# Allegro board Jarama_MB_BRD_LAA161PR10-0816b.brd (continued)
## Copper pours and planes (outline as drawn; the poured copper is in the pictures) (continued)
DCIN_GND on TOP (solid shape): 33.84,68.97 33.84,67.17 33.58,66.91 30.03,66.91 29.52,67.42 29.52,68.69 29.9,69.07 33.74,69.07
DCIN_GND on BOTTOM (solid shape): 33.85,68.94 33.85,65.51 33.72,65.39 32.07,65.39 30.68,66.78 30.68,68.94 30.8,69.07 33.72,69.07
DH_+1.2V on TOP (solid shape): 87.31,31.53 87.31,30.56 87.23,30.49 86.39,30.49 86.29,30.59 86.29,31.48 86.42,31.61 87.23,31.61
DH_+1.2V on BOTTOM (solid shape): 95.69,33.83 94.85,33.83 94.56,33.54 94.56,33.43 94.46,33.33 93.56,33.33 93.42,33.47 93.42,33.83 93.63,34.04 95.69,34.04
DH_+1.2V on IN1 (solid shape): 87.57,32.24 87.57,30.59 87.19,30.21 86.68,30.21 86.43,30.46 86.43,32.24 86.56,32.37 87.45,32.37
DH_+1.2V on IN1 (solid shape): 94.81,34.02 94.81,33.51 94.56,33.26 92.65,33.26 92.4,33.51 92.4,34.15 92.53,34.27 94.56,34.27
DL_+1.2V on TOP (solid shape): 88.38,34.98 88.38,33.85 88.29,33.76 87.56,33.76 87.31,34.02 87.31,34.6 87.21,34.7 87.21,35.08 87.29,35.16 88.19,35.16
DL_+1.2V on BOTTOM (solid shape): 96.13,33.1 96.13,32.39 95.37,31.63 94.89,31.63 94.68,31.83 94.68,31.99 95.83,33.13 96.11,33.13
DL_+1.2V on IN3 (solid shape): 89.35,34.65 89.35,34.02 89.22,33.89 87.83,33.89 87.32,34.4 87.32,35.03 87.45,35.16 88.84,35.16
DL_+1.2V on IN3 (solid shape): 95.83,32.49 95.83,31.86 95.07,31.1 94.05,31.1 94.05,32.11 94.43,32.11 95.07,32.75 95.57,32.75
HP2_D_R_C on TOP: 13.14,15.98 15.27,15.98 15.32,15.93 15.32,14.87 15.53,14.66 15.8,14.66 16.03,14.44 16.03,13.93 15.75,13.65 14.79,13.65 14.08,14.36 14.08,14.74 13.99,14.83 12.33,14.83 12.33,15.17
KB_LED_PWM# on BOTTOM: 155.01,8.75 156.66,8.75 156.91,9 156.91,10.27 157.17,10.52 157.17,11.16 157.17,11.16 157.17,11.44 156.88,11.72 156.23,11.72 156.03,11.92 155.14,11.92 154.88,11.67 154.88,8.87
L_MIC1 on TOP (solid shape): 21.38,24.2 22.14,24.2 22.23,24.11 22.66,24.11 22.75,24.2 23.72,24.2 23.74,24.19 23.74,24.01 23.72,24 22.88,24 22.79,23.91 21.24,23.91 21.12,23.79 20.24,23.79 20.06,23.97 20.06,24.54 20.35,24.82 20.76,24.82
L_MIC1 on IN1 (solid shape): 16.45,6.28 16.45,5.29 16.32,5.17 14.82,5.17 14.68,5.3 14.68,6.23 14.84,6.4 16.33,6.4
L_MIC1 on BOTTOM: 16.09,5.15 15.83,5.41 15.83,6.32 16.87,7.36 16.87,8.53 15.7,9.71 15.7,10.16 15.96,10.42 17.12,10.42 17.28,10.58 17.28,12.8 17.3,12.81 18.55,12.81 18.76,13.02 19.59,13.02 19.74,12.87 19.74,10.07 18.71,9.04 18.71,6.19 17.66,5.15
L_MIC1 on IN1: 19.17,13.88 18.58,13.28 18.58,12.58 18.98,12.17 23.42,12.17 23.7,12.46 23.7,24.71 23.42,24.99 20.43,24.99 19.99,24.55 19.99,20.32 19.17,19.51
L_MIC1 on IN2: 3.22,1.49 2.54,2.17 2.54,4.18 2.8,4.44 3.96,4.44 4.22,4.18 4.22,3.54 4.52,3.24 10.47,3.24 12.05,4.82 12.25,5.22 12.1,5.63 14.17,7.7 15.49,7.7 17.24,9.45 17.24,13.3 20.96,17.02 20.96,20.19 22.66,21.89 22.66,23.85 22.58,23.93 20.86,23.93 20.61,23.68 20.05,23.68 19.84,23.89 19.84,25.59 20.48,26.23 23.44,26.23 23.73,25.93 23.73,16.68 20.09,13.04 20.09,8.31 16.97,5.2 14.04,5.2 10.33,1.49
LG_3V on TOP (solid shape): 192.87,37.55 192.87,37.22 191.45,35.8 191.32,35.8 191.26,35.86 191.26,36.72 191.32,36.79 191.52,36.79 191.67,36.94 191.67,37.5 191.83,37.65 192.77,37.65
LG_3V on TOP (solid shape): 193.5,44.64 193.5,44.43 193.15,44.08 193.15,43.32 193,43.16 192.54,43.16 192.39,43.32 192.39,44.66 192.51,44.79 193.35,44.79
LG_3V on IN2 (solid shape): 194.45,45.64 194.45,44.83 194.37,44.76 193.71,44.76 193.59,44.64 193.59,44.46 193.47,44.33 193.34,44.33 192.75,43.75 192.53,43.75 192.4,43.87 192.4,44.23 192.32,44.31 192.32,44.72 193.4,45.8 194.29,45.8
LG_3V on IN2 (solid shape): 192.83,38.16 192.6,37.93 192.6,37.24 192.45,37.09 191.48,37.09 191.45,37.13 191.53,37.43 191.36,37.69 191.36,38.59 191.84,39.07 192.83,39.07
LG_5V on TOP (solid shape): 189.46,40.72 189.46,36.99 189.67,36.79 189.79,36.79 189.86,36.72 189.86,35.82 189.8,35.76 189.68,35.76 188.74,36.7 188.74,38.76 187.51,39.99 187.51,40.8 187.69,40.98 189.21,40.98
LINE2-VREFO on TOP (solid shape): 22.89,25.03 23.83,25.03 23.91,24.95 23.91,24.85 23.83,24.77 22.84,24.77 22.76,24.85 22.36,24.85 21.88,24.37 21.47,24.37 21.29,24.54 21.29,24.72 21.49,24.93 22.13,24.93 22.26,25.05 22.87,25.05
LX_3V on TOP (solid shape): 196.55,44.26 196.55,43.77 195.94,43.16 195.51,43.16 195.38,43.29 195.38,44.18 195.51,44.31 196.5,44.31
LX_3V on TOP (solid shape): 194.77,35.23 194.77,34.23 194.71,34.17 193.3,34.17 192.79,34.68 191.75,34.68 191.75,34.83 191.8,34.88 193.12,34.88 193.58,35.34 194.66,35.34
LX_3V on IN1 (solid shape): 195.2,36.67 195.2,35.55 193.84,34.2 193.58,34.2 193.19,34.6 193.19,35.3 194.18,36.29 194.18,36.6 194.38,36.8 195.07,36.8
LX_3V on IN1 (solid shape): 196.68,44.37 196.68,43.81 196.18,43.31 196.18,41.74 196.15,41.71 195.19,41.71 195.16,41.74 195.16,44.22 195.49,44.54 196.51,44.54
LX_5V on TOP (solid shape): 185.22,40.88 185.22,40.06 185.1,39.94 184.33,39.94 184.21,40.06 184.21,40.64 184.58,41 185.1,41
LX_5V on TOP (solid shape): 187.89,34.88 189.52,34.88 189.58,34.82 189.58,34.74 189.52,34.68 188.35,34.68 187.64,33.97 186.61,33.97 186.48,34.09 186.48,35.03 186.51,35.06 187.71,35.06
LX_5V on IN2 (solid shape): 185.39,40.32 185.39,38.51 187.9,36 187.9,34.23 187.52,33.84 186.73,33.84 186.4,34.17 186.4,35.64 184.04,38.01 184.04,40.57 184.09,40.62 185.08,40.62
LX_DGPU on BOTTOM (solid shape): 100.78,51.8 100.78,46.94 100.77,46.94 100.34,46.68 100.55,46.22 100.38,46.08 100.31,45.87 98.24,43.8 94.61,43.8 94.61,42.99 97.12,42.99 97.12,41.28 96.59,40.75 93.92,40.75 93.54,41.13 93.54,44.43 94.94,45.83 94.94,47.23 97,49.29 97.79,49.29 97.99,49.49 97.99,52.03 98.03,52.07 100.51,52.07
MIC2-VREFO-L on TOP (solid shape): 29.83,22.15 29.83,21.32 29.72,21.22 28.89,21.22 28.78,21.32 28.78,22.16 28.84,22.21 29.77,22.21
P1 on TOP (solid shape): 77.65,14.97 77.65,11.67 77.4,11.41 74.1,11.41 73.79,11.72 73.79,13.5 73.87,13.57 75.37,13.57 75.49,13.7 75.49,14.33 73.72,14.33 73.72,15.1 77.53,15.1
REGN on TOP (solid shape): 97.47,8.36 97.47,7.81 97.72,7.55 97.72,6.84 97.59,6.71 96.83,6.71 96.45,7.09 95.56,7.09 95.43,7.22 95.43,7.6 96.45,8.62 97.21,8.62
REGN on BOTTOM (solid shape): 97.86,8.39 97.86,7.48 97.78,7.4 97.68,7.4 97.53,7.55 97.15,7.55 96.87,7.83 96.87,8.52 96.95,8.59 97.66,8.59
SKIP#1 on BOTTOM (solid shape): 100.07,55.29 100.07,53.75 100.06,53.74 99.11,53.74 98.91,53.54 98.91,53.14 98.82,53.04 98.06,53.04 97.99,53.12 97.99,54.14 99.21,55.36 100,55.36
SLEEVE on IN1 (solid shape): 16.73,11.16 16.73,10.97 16.21,10.45 15.98,10.45 14.65,11.78 14.65,12.06 15.11,12.52 15.37,12.52
SLEEVE on TOP: 15.68,15.9 15.68,18.65 15.8,18.78 16.44,18.78 16.57,18.65 16.57,16.87 16.69,16.75 16.74,16.75 16.9,16.59 16.9,16.36 17.05,16.21 17.05,15.93 16.89,15.77 15.81,15.77
SLEEVE on TOP: 21.61,23.8 23.73,23.8 23.74,23.79 23.74,23.61 23.73,23.6 22.74,23.6 22.45,23.31 21.64,23.31 21.52,23.43 21.52,23.71
SLEEVE on TOP: 14.88,12.84 15.64,12.84 16.63,11.85 16.63,10.74 16.47,10.57 16.2,10.57 15.09,11.67 14.8,11.67 14.47,12 14.47,12.43
SLEEVE on BOTTOM: 16.49,17.58 16.49,17.18 16.14,16.83 16.14,16.02 16.3,15.86 16.95,15.86 17.03,15.93 17.03,16.6 17.39,16.97 17.39,17.48 17.21,17.67 16.58,17.67
SLEEVE on IN2: 19.81,17.61 19.81,19.85 22.57,22.61 22.57,23.66 22.45,23.78 20.87,23.78 20.22,23.13 19.05,23.13 17.99,22.07 17.99,21.22 15.82,19.05 15.82,17.71 13.92,15.8 8.79,15.8 7.66,14.68 2.93,14.68 2.38,14.14 2.38,12.45 2.67,12.16 4.01,12.16 4.27,12.42 4.27,13.12 4.75,13.59 15.79,13.59
SNUB_1.5VSP on BOTTOM (solid shape): 90.49,52.05 90.49,50.4 90.37,50.27 89.48,50.27 89.48,50.91 88.97,51.42 88.97,52.18 90.37,52.18
SNUB_1.8VSP on BOTTOM (solid shape): 224.83,36.36 224.83,35.56 224.77,35.49 221.89,35.49 221.79,35.59 221.79,36.47 221.93,36.61 224.58,36.61
SNUB_3V on BOTTOM (solid shape): 195.6,46.9 195.6,45.91 195.55,45.86 194.58,45.86 194.25,45.53 194.25,45.02 193.26,45.02 193.16,45.12 193.16,46.8 193.34,46.97 195.52,46.97
SNUB_5V on BOTTOM (solid shape): 187.13,46.91 187.13,45.29 187.09,45.25 186.12,45.25 186,45.37 186,45.7 185.74,45.96 184.85,45.96 184.73,46.08 184.73,46.85 184.85,46.97 187.07,46.97
SNUB_+1.2V on BOTTOM (solid shape): 90.37,38.97 90.37,38.21 90.87,37.7 90.87,36.81 89.35,36.81 89.22,36.94 89.22,39.1 89.35,39.23 90.11,39.23
SNUB_+1.05V on BOTTOM (solid shape): 198.27,63.63 198.27,61.83 198.21,61.77 197.71,61.77 197.7,61.78 197.7,62.45 197.56,62.59 196.59,62.59 196.55,62.64 196.55,63.69 196.6,63.74 198.16,63.74
SNUB_CHG on BOTTOM (solid shape): 88.82,14.23 88.82,13.93 89.05,13.7 89.93,13.7 90.04,13.6 90.04,12.58 89.88,12.43 87.83,12.43 87.57,12.68 87.57,14.38 87.7,14.51 88.54,14.51
SPK_L+_C on TOP (solid shape): 20.79,15.41 21.03,15.35 21.27,15.42 23.5,15.42 24.27,14.65 24.27,13.8 24.66,13.41 24.66,12.77 24.63,12.74 23.61,12.74 23.5,12.84 23.5,13.79 22.71,14.58 21.18,14.58 21.09,14.49 21.06,14.49 21.06,14.46 20.94,14.34 20.68,14.34 20.58,14.44 20.58,15.34 20.66,15.42 20.78,15.42
SPK_L+_C on BOTTOM: 21.53,10.55 20.39,11.69 20.39,16.73 20.4,16.74 20.4,17.22 20.5,17.33 21.38,17.33 21.61,17.1 21.61,15.52 21.32,15.22 21.32,13.65 22.55,12.42 22.55,10.73 22.37,10.55
SPK_L-_C on TOP: 21.24,12.71 21.95,12.71 22.15,12.5 23.08,12.5 23.21,12.63 23.21,13.69 22.5,14.39 22.13,14.39 22.07,14.33 22.07,13.68 21.83,13.45 21.25,13.45 21.21,13.4 21.21,12.74
SPK_L-_C on BOTTOM: 23.13,10.52 23.56,10.52 23.82,10.78 23.82,17 23.44,17.38 22.57,17.38 22.45,17.25 22.45,15.05 22.72,14.78 22.72,12.89 22.99,12.61 22.99,10.66
SPK_OUT_L+ on TOP (solid shape): 24.92,12 24.92,11.86 25.94,10.85 25.94,9.02 25.87,8.95 25.73,8.95 25.67,9.01 25.67,9.85 25.67,9.85 25.67,9.92 24.16,11.43 23.7,11.43 23.57,11.56 23.57,12.19 23.62,12.24 24.68,12.24
SPK_OUT_L- on TOP (solid shape): 22.59,11.98 22.59,11.69 24.86,9.42 24.86,8.44 24.78,8.36 23.88,8.36 23.68,8.57 23.68,9.29 22.85,10.12 22.38,10.12 21.24,11.26 21.24,12.15 21.3,12.21 22.36,12.21
SPK_OUT_R+ on TOP (solid shape): 26.94,11.9 26.94,11.89 27.09,11.74 27.09,10.19 26.94,10.03 26.94,9.02 26.86,8.94 26.74,8.94 26.67,9.01 26.67,10.08 26.67,10.08 26.67,10.45 25.6,11.52 25.6,12.11 25.68,12.19 26.64,12.19
SPK_OUT_R- on TOP (solid shape): 28.82,11.95 28.82,8.46 28.72,8.37 27.81,8.37 27.76,8.43 27.76,10.9 27.42,11.24 27.42,12.15 27.5,12.22 28.55,12.22
SPK_R+_C on TOP (solid shape): 26.27,16.6 26.27,13.84 26.7,13.4 26.7,12.71 26.68,12.68 25.48,12.68 25.37,12.79 25.37,13.62 25.3,13.69 25.3,16.7 25.43,16.83 26.04,16.83
SPK_R+_C on BOTTOM: 24.81,10.55 24.45,10.55 24.25,10.75 24.25,16.75 24.8,17.29 25.66,17.29 26.13,16.82 26.13,15.79 25.33,14.99 25.33,12.72 25.05,12.44 25.05,10.79
SPK_R-_C on TOP (solid shape): 28.52,15.37 28.52,12.7 28.49,12.66 27.49,12.66 27.43,12.72 27.43,14.47 27.3,14.61 27.3,15.41 27.49,15.6 28.29,15.6
SPK_R-_C on BOTTOM: 26.24,10.52 25.71,10.52 25.51,10.73 25.51,12.38 26.61,13.48 26.61,15.41 26.4,15.63 26.4,17.12 26.63,17.34 27.36,17.34 27.5,17.2 27.5,15.83 27.82,15.52 27.82,13.11 26.49,11.78 26.49,10.77
SW_+1.2V on TOP (solid shape): 93.35,33.1 94.57,33.1 94.67,33 94.67,32.24 94.47,32.04 92.57,32.04 92.34,32.27 91.87,32.27 91.59,31.99 90.86,31.99 90.61,31.73 90.61,29.07 90.2,28.66 83.95,28.66 83.5,29.12 83.5,30.97 84,31.48 85.91,31.48 86.04,31.35 86.04,30.51 86.21,30.34 87.56,30.34 87.69,30.46 87.69,33.43 87.76,33.51 92.94,33.51
SW_+1.2V on BOTTOM (solid shape): 95.73,33.51 95.73,33.28 93.99,31.54 92.51,31.54 92.51,32.44 92.53,32.45 93,32.45 93.73,33.18 94.63,33.18 94.84,33.38 94.84,33.54 94.89,33.59 95.65,33.59
SW_+1.2V on BOTTOM (solid shape): 90.87,33.06 89.85,32.04 89.85,31.47 90,31.33 90,29.05 89.63,28.68 83.91,28.68 83.48,29.12 83.48,31.76 86.66,31.76 86.66,30.44 86.76,30.34 87.34,30.34 87.46,30.45 87.46,31.77 87.36,31.87 86.77,31.87 86.66,31.76 83.48,31.76 83.48,33.79 84.04,34.35 88.57,34.35 89.26,35.03 90.87,35.03
SW_+1.05VS on TOP (solid shape): 196.14,64.8 196.14,62.47 196.02,62.34 194.6,62.34 194.44,62.19 192.4,62.19 192.12,62.46 192.12,63.23 192.12,63.31 192.93,64.12 192.93,64.59 193.23,64.89 196.05,64.89
SW_+1.05VS on BOTTOM (solid shape): 199.46,66 199.46,64.63 199.21,64.37 196.92,64.37 196.31,63.76 196.31,59.63 196.1,59.42 194.32,59.42 194.12,59.62 194.12,60.31 193.62,60.82 193.62,61.45 193.24,61.83 192.35,61.83 192.12,62.06 192.12,63.01 192.6,63.49 192.6,64.96 193.97,66.33 199.13,66.33
UG_3V on TOP (solid shape): 193.66,36.89 193.66,36.25 193.55,36.15 193.15,36.15 192.46,35.47 191.6,35.47 191.55,35.52 191.55,35.64 192.97,37.07 193.48,37.07
UG_3V on TOP (solid shape): 196.93,43.32 196.93,42.43 196.75,42.25 196.35,42.25 196.09,42.5 195.64,42.5 195.48,42.65 195.48,42.83 195.59,42.93 196.07,42.93 196.55,43.42 196.83,43.42
UG_3V on BOTTOM (solid shape): 196.79,43.29 196.79,42.25 196.36,41.82 196.36,38.9 193.57,36.1 192.53,36.1 192.42,36.2 192.42,36.82 192.59,36.99 192.87,37.1 192.98,37.38 195.34,39.74 195.34,43.06 195.73,43.44 196.65,43.44
UG_5V on TOP (solid shape): 185.2,41.54 185.2,41.31 185.12,41.23 184.46,41.23 183.98,40.75 183.98,39.99 186.11,37.85 187.36,37.85 189.58,35.63 189.58,35.54 189.52,35.48 188.51,35.48 187.36,36.64 185.76,36.64 182.89,39.51 182.89,41.18 183.34,41.64 185.1,41.64
VLDOIN_+1.2V on BOTTOM (solid shape): 94.6,35.84 94.6,35.03 94.8,34.84 95.74,34.84 95.78,34.8 95.78,34.69 95.73,34.63 93.68,34.63 93.52,34.79 93.52,36.07 93.54,36.09 94.35,36.09
VRP on TOP: 24.64,21.88 24.69,21.83 24.69,20.56 24.57,20.43 24.57,20.05 24.19,19.67 22.92,19.67 22.79,19.79 22.79,20.18 23.04,20.43 24.06,20.43 24.44,20.81 24.44,21.83 24.49,21.88
VRP on BOTTOM: 24.96,18.14 24.58,17.76 23.18,17.76 22.8,18.14 22.8,20.21 22.92,20.33 24.72,20.33 24.96,20.09
N13374678 on TOP (solid shape): 196.12,58.83 196.56,58.39 196.56,58.31 196.91,57.97 196.91,57.51 197.16,57.26 197.67,57.26 197.8,57.13 197.8,56.62 197.67,56.5 197.16,56.5 197.03,56.62 197.03,56.88 196.91,57.01 196.14,57.01 195.94,57.21 195.94,59.72 196.12,59.72
N13374846 on TOP (solid shape): 197.54,66.15 197.54,65.39 197.41,65.26 196.54,65.26 196.31,65.49 195.2,65.49 195.12,65.58 195.12,66.21 195.18,66.28 197.41,66.28
N22841841 on TOP: 53.57,12.91 55.45,12.91 55.56,12.81 55.56,11.92 55.48,11.84 53.49,11.84 53.36,11.97 53.36,12.7
N39955939 on BOTTOM: 35.38,14.33 36.26,14.33 36.89,13.71 36.89,12.78 36.52,12.42 36.52,12.12 36.46,12.06 35.6,12.06 35.5,12.16 35.5,13.06 35.25,13.32 35.25,14.21
N39956029 on BOTTOM: 33.72,14.33 33.85,14.21 33.85,13.46 33.76,13.36 32.75,13.36 32.64,13.47 31.77,13.47 31.69,13.55 31.69,14.21 31.82,14.33
N42153733 on TOP (solid shape): 244.14,54.35 244.14,54.32 244.15,54.28 244.15,52.85 243.99,52.69 243.97,52.69 243.8,52.51 243.15,52.51 243.03,52.63 243.03,54.16 243.25,54.38 244.11,54.38
N43167321 on TOP (solid shape): 194.87,51.47 194.87,50.62 194.84,50.58 193.5,50.58 193.32,50.76 191.9,50.76 191.83,50.83 191.83,51.47 191.95,51.6 194.75,51.6
N43454026 on TOP (solid shape): 168.33,67.55 168.33,67.4 168.7,67.04 169.6,67.04 169.73,66.91 169.73,66.4 169.6,66.28 168.71,66.28 168.01,66.98 167.38,66.98 167.38,67.61 168.27,67.61
N44367556 on TOP (solid shape): 192.67,49.34 193.12,49.34 193.22,49.23 193.22,48.52 193.12,48.42 191.98,48.42 191.83,48.57 191.83,49.31 191.95,49.44 192.56,49.44
N44367556 on BOTTOM (solid shape): 193.24,49.44 193.24,48.9 193.28,48.85 193.28,48.63 193.14,48.49 192.11,48.49 191.96,48.64 191.96,49.51 192.01,49.56 193.11,49.56
N44369635 on TOP (solid shape): 190.61,49.34 190.61,48.45 190.3,48.14 188.19,48.14 188.02,48.32 188.02,49.06 188.14,49.18 189.57,49.18 189.76,49.38 190.57,49.38
N44369635 on BOTTOM (solid shape): 190.82,49.94 190.82,48.75 190.7,48.62 188.66,48.62 188.54,48.75 188.54,49.39 188.79,49.64 189.81,49.64 189.93,49.77 189.93,49.89 190.11,50.07 190.7,50.07
N44372336 on TOP: 243.08,51.2 243.9,51.2 244.51,51.81 245.15,51.81 245.23,51.73 245.23,50.83 245.02,50.63 244.02,50.63 243.86,50.47 243.13,50.47 243.03,50.57 243.03,51.15
N44536141 on TOP (solid shape): 169.73,69.58 169.73,68.56 169.6,68.44 167.44,68.44 167.32,68.56 167.32,69.45 167.57,69.71 169.6,69.71
N45346908 on TOP: 51.11,10.14 51.11,8.63 50.13,7.65 48.14,7.65 48.05,7.74 48.05,8.35 48.15,8.45 49.42,8.45 49.59,8.62 49.59,9.63 49.84,9.89 49.84,10.52 49.97,10.65 50.48,10.65 50.6,10.52 50.6,10.4 50.73,10.27 50.98,10.27
N45347302 on TOP: 238.18,47.23 236.66,47.23 236.53,47.1 236.53,46.21 236.91,45.83 238.56,45.83 238.69,45.96 238.69,46.72
N45348400 on TOP: 237.29,50.66 236.53,50.66 236.4,50.53 236.4,49.39 236.53,49.26 236.53,48.62 236.66,48.5 237.17,48.5 237.42,48.75 237.42,50.53
N47396970 on BOTTOM (solid shape): 229.05,38.84 229.05,37.57 228.82,37.35 225.37,37.35 225.09,37.63 225.09,39.68 225.29,39.89 228.01,39.89
N47396970 on TOP: 227.13,36.79 227.13,37.7 227.39,37.96 228.26,37.96 228.34,38.03 228.34,38.87 228.34,38.88 228.25,38.97 226.79,38.97 226.52,38.71 226.36,38.71 226.1,38.97 225.15,38.97 225.08,39.05 225.08,40.17 225.25,40.34 228.72,40.34 229.05,40 229.05,39.67 229.83,38.89 229.83,37.32 229.3,36.79
N47421956 on TOP (solid shape): 104.34,61.12 104.96,61.12 105.09,60.99 105.09,60.36 105.04,60.31 104.48,60.31 104.43,60.36 104.43,60.49 104.22,60.69 103.82,60.69 103.56,60.43 103.56,60.31 103.43,60.18 102.67,60.18 102.62,60.23 102.62,60.33 102.67,60.38 102.67,61.1 103.03,61.45 104.01,61.45
N47421965 on TOP (solid shape): 99.47,59.19 99.47,59.06 99.42,59.01 98.18,59.01 98.02,58.86 98.02,58.81 97.54,58.33 97.54,57.67 97.14,57.26 95.18,57.26 95.05,57.13 95.05,56.33 94.89,56.17 94.19,56.17 94.16,56.19 94.16,57.34 94.3,57.47 94.54,57.47 94.63,57.56 96.37,57.56 96.48,57.67 96.48,58.53 96.83,58.89 97.62,58.89 97.95,59.22 99.45,59.22
N47422085 on TOP (solid shape): 100.16,57.26 100.16,55.74 100.51,55.38 100.51,54.77 100.36,54.62 98.46,54.62 98.3,54.77 98.3,55.33 98.35,55.38 99.55,55.38 99.93,55.76 99.93,57.26 100.01,57.34 100.08,57.34
N47422365 on BOTTOM (solid shape): 102.05,49.89 102.05,47.23 101.92,47.1 101.03,47.1 100.91,47.23 100.91,49.89 101.03,50.02 101.92,50.02
N47972306 on TOP: 195.26,52.94 196.14,52.94 196.4,52.69 196.4,51.54 196.53,51.42 196.53,50.66 195.64,50.66 195.13,51.16 195.13,52.81
N48463842 on TOP: 13.26,9.89 14.53,9.89 14.79,9.63 15.8,9.63 16.06,9.89 16.06,10.42 15.58,10.9 14.66,10.9 14.28,11.29 13.65,11.29 13.14,10.78 13.14,10.02
N48664246 on TOP (solid shape): 28.25,59.34 28.25,55.74 28.12,55.61 28.12,54.97 28,54.85 27.36,54.85 27.23,54.97 27.23,57.74 27.39,57.89 27.39,59.32 27.49,59.42 28.17,59.42
N48664254 on TOP (solid shape): 33.74,58.53 33.74,57.01 33.56,56.83 29.65,56.83 29.47,57.01 28.76,57.01 28.5,57.26 28.5,58.35 28.61,58.45 29.17,58.45 29.44,58.73 33.53,58.73
N48664254 on BOTTOM (solid shape): 30.04,58.4 30.04,57.26 29.94,57.16 28.6,57.16 28.39,57.37 28.39,58.4 28.64,58.66 29.79,58.66
N48664258 on TOP (solid shape): 72.7,14.97 72.7,14.33 71.05,14.33 70.92,14.21 70.92,13.57 72.7,13.57 72.7,12.05 72.45,11.79 68.64,11.79 67.75,12.68 67.75,14.46 68.38,15.1 72.57,15.1
N48664258 on TOP: 31.12,56.62 31.12,50.55 31.17,50.02 31.43,49.77 33.58,49.77 33.86,50.05 33.86,53.88 32.95,54.8 32.95,56.56 32.88,56.62 31.13,56.62
N48664258 on VCC: 51.84,10.14 51.67,10.32 48.93,13.06 45.12,13.06 33.96,24.24 33.58,24.24 33.34,24.47 33.34,24.85 31.18,27.01 31.18,40.86 30.55,41.49 30.55,42.17 31.18,42.8 31.18,51.44 31.29,51.54 34.13,51.54 34.13,37.58 34.14,37.58 46.55,16.68 70.86,16.74 70.86,13.23 68.02,10.4 53.58,10.4 53.33,10.14
N48664258 on IN2: 53.16,11.54 51.76,12.94 45.79,12.94 37.41,21.32 37.41,22.08 35.25,25.76 33.85,28.68 33.85,29.57 33.72,29.7 33.72,30.34 33.47,30.84 32.33,35.13 32.33,41 31.82,41.51 31.82,43.92 32.2,44.31 32.2,45.32 31.18,46.34 31.18,51.42 31.31,51.54 33.72,51.54 33.85,51.42 33.85,36.43 34.08,34.63 34.36,33 34.61,31.73 35.25,29.7 36.01,27.8 36.77,26.27 37.41,25.13 38.26,23.94 38.49,23.6 38.74,23.27 39.31,22.46 40.2,21.45 41.34,20.18 42.49,19.16 44.14,17.89 45.03,17.25 46.3,16.49 47.69,15.73 49.09,15.1 51.5,14.21 53.54,13.7 54.43,13.57 55.19,13.44 55.82,13.32 56.46,13.32 56.86,13.29 57.6,13.24 58.13,13.22 58.9,13.22 59.71,13.24 60.39,13.27 60.47,13.29 60.72,13.32 61.33,13.37 61.77,13.42 61.92,13.44 62.48,13.52 62.96,13.6 63.49,13.7 64.08,13.83 64.94,14.03 65.73,14.26 66.62,14.54 67.86,14.99 68.98,15.48 70.05,15.98 70.3,15.98 70.94,15.35 70.94,13.32 68.27,10.65 54.04,10.65 54.04,10.78 53.28,11.54
N48664262 on TOP (solid shape): 29.39,56.62 30.92,56.62 30.92,55.99 28.63,55.99 28.63,56.75 29.27,56.75
N48664277 on BOTTOM (solid shape): 104.59,8.87 104.59,7.09 104.21,6.71 103.7,6.71 102.2,8.21 102.2,9.86 102.23,9.89 103.57,9.89
N48664377 on TOP (solid shape): 85.78,17.76 85.78,13.32 85.65,13.19 82.1,13.19 81.84,12.94 81.84,11.41 78.16,11.41 78.03,11.54 78.03,15.1 80.96,18.02 85.53,18.02
N48664377 on BOTTOM (solid shape): 82.11,15.1 82.11,11.67 81.73,11.29 79.83,11.29 79.06,12.05 79.06,16.11 79.44,16.49 80.71,16.49
N48665076 on BOTTOM (solid shape): 92.91,4.3 92.91,3.41 92.65,3.16 92.14,3.16 92.02,3.28 92.02,3.67 91.89,3.79 91,3.79 90.87,3.92 90.87,4.43 91,4.55 92.65,4.55
N48665393 on BOTTOM (solid shape): 107.64,11.79 107.64,10.27 107.51,10.14 104.84,10.14 104.72,10.27 104.72,11.79 104.84,11.92 107.51,11.92
N48850801 on TOP (solid shape): 192.21,44.36 192.21,43.04 192.33,42.91 192.97,42.91 193.1,42.78 193.1,40.88 192.97,40.75 190.68,40.75 190.43,41 190.43,44.38 190.58,44.53 192.03,44.53
N48850801 on BOTTOM (solid shape): 192.2,46.77 192.2,43.77 192.42,43.54 193.11,43.54 193.36,43.29 193.36,39.61 193.24,39.48 190.95,39.48 190.82,39.61 190.82,40.5 190.44,40.88 190.44,46.8 190.62,46.97 191.99,46.97
N48850937 on TOP (solid shape): 190.18,44.2 190.18,41.38 190.05,41.26 187.64,41.26 187.51,41.38 187.51,44.26 187.79,44.53 189.85,44.53
N48850937 on BOTTOM (solid shape): 190.19,46.46 190.19,40.93 189.81,40.55 189.81,39.63 189.53,39.35 187.52,39.35 187.39,39.48 187.39,46.85 187.52,46.97 189.68,46.97
N49081818 on TOP: 201.81,8.54 202.39,8.54 202.95,9.1 204.27,9.1 204.43,8.95 204.43,8.42 203.13,7.12 202.04,7.12 201.73,7.43 201.73,8.47
N49301672 on TOP (solid shape): 191.08,38.58 191.08,37.87 190.7,37.49 190.7,36.78 190.66,36.74 190.66,35.8 190.62,35.76 190.5,35.76 190.46,35.8 190.46,36.75 190.43,36.77 190.43,37.5 190.05,37.88 190.05,38.59 190.18,38.72 190.94,38.72
N51254722 on BOTTOM (solid shape): 15.79,20.88 15.79,20.02 15.61,19.84 14.2,19.84 14.11,19.93 14.11,20.29 14.46,20.64 14.46,21.03 14.48,21.06 15.61,21.06
N53088164 on BOTTOM (solid shape): 91.95,33.64 91.95,33.03 92.37,32.62 92.37,31.62 92.23,31.48 91.19,31.48 91.07,31.61 91.07,33.64 91.19,33.76 91.83,33.76

Small or netless copper shapes (teardrops, artwork), in the pictures only: 87 on TOP, 19 on BOTTOM, 34 on IN1, 4 on IN2, 15 on IN3, 31 on IN4

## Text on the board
Ref Des/Silkscreen Bottom: H11 | H9 | A | H26
User.Comments: LA-A161P | Fisher_Chen | 2013-08-16 | 2014-08-16 | VAZ90 | 1.0(A00)
Ref Des/Silkscreen Top: A | H15
USER_PART_NUM_TOP: FIGURE | SIZE | 4.0 | DRILL CHART: TOP to GND1 | ALL UNITS ARE IN MILS | PLATED | QTY | 247
USER_PART_NUM_BOTTOM: 1.0mm_2+6+2(50ohm)(Top Gnd In1 G-V In2 In3 G-V In4 Gnd Bot)-121116.pdf | 7.5 | 5 | 4.3 | 3 | 4 | 8.1/4 | 6.5/5.7 | 4.3/4.5 | 3/3 | 4.3/6.2 | 3/4
COMPVAL_TYPE_TOP: FIGURE | SIZE | 8.0 | 10.0 | 22.0 | 30.0 | 31.0 | 94.0 | 118.0 | 130.0 | 154.0 | 35.0 | 39.0 | 40.0 | 43.0 | 63.0 | 31.0x16.0 | 55.0x24.0 | 67.0x31.0 | 87.0x20.0 | 87.0x31.0 | 94.0x31.0 | 94.0x63.0 | DRILL CHART: TOP to BOTTOM | ALL UNITS ARE IN MILS | PLATED | NON-PLATED | QTY | 2177 | 187 | 602 | 19 | 2 | 18 | 6 | 1 | 4 | 3 | 26 | 7 | 8
User.9: FIGURE | SIZE | 4.0 | DRILL CHART: GND3 to BOTTOM | ALL UNITS ARE IN MILS | PLATED | QTY | 317
User.10: FIGURE | SIZE | 8.0 | DRILL CHART: IN1 to IN4 | ALL UNITS ARE IN MILS | PLATED | QTY | 672
User.11: FIGURE | SIZE | 4.0 | DRILL CHART: IN4 to BOTTOM | ALL UNITS ARE IN MILS | PLATED | QTY | 906
User.12: FIGURE | SIZE | 4.0 | DRILL CHART: TOP to IN1 | ALL UNITS ARE IN MILS | PLATED | QTY | 407
User.13: FIGURE | SIZE | 4.0 | DRILL CHART: GND1 to IN1 | ALL UNITS ARE IN MILS | PLATED | QTY | 1
User.31: IN5
User.32: GND4
